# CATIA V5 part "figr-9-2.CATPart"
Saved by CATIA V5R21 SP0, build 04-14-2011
Part number: Part1
Bounding box of the stored display mesh (mm): x -25 to 69.61, y -139.735 to 0, z 0 to 45
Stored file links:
  D:\CATIA V5R21 E-RESOURCES\CATIA-V5R21\catia-v5r21-prt\c09-catia-v5r20-prt\c09-catia-v5r21-figr-9-2.CATPart
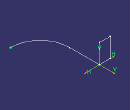
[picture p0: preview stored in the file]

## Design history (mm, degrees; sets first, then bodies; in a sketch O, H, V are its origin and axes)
Body1 (main body)
  Sketch1 on xy-plane, origin (0, 0, 0), H (1, 0, 0), V (0, 1, 0)
    line L1 (0, 0) -> (0, -70.1255)
    arc A1 centre (69.6095, -70.1255) radius 69.6095 from (0, -70.1255) to (69.6095, -139.7351) ccw
    vertical: L1 V
    tangency: A1 L1
  Sketch2 on zx-plane, origin (0, 0, 0), H (-1, 0, 0), V (0, 0, 1)
    point P1 (0, 0)
    line L1 (0, 0) -> (25, 0)
    line L2 (25, 0) -> (25, 45)
    line L3 (25, 45) -> (0, 45)
    line L4 (0, 45) -> (0, 0)
    length L3 = 25
    length L2 = 45
    coincidence: P1 H, P1 O
    horizontal: L1 H, L3 H
    vertical: L2 V, L4 V
  Rib1: profile Sketch2, centre curve Sketch1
